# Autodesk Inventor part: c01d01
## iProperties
Created: 2004-05
Part Number: c01d01
Document SubType Name: Modeling
Designer: CADCIM Technologies
Manufacturer: Standard
Standards Organization: Custom
Author: CADCIM Technologies
